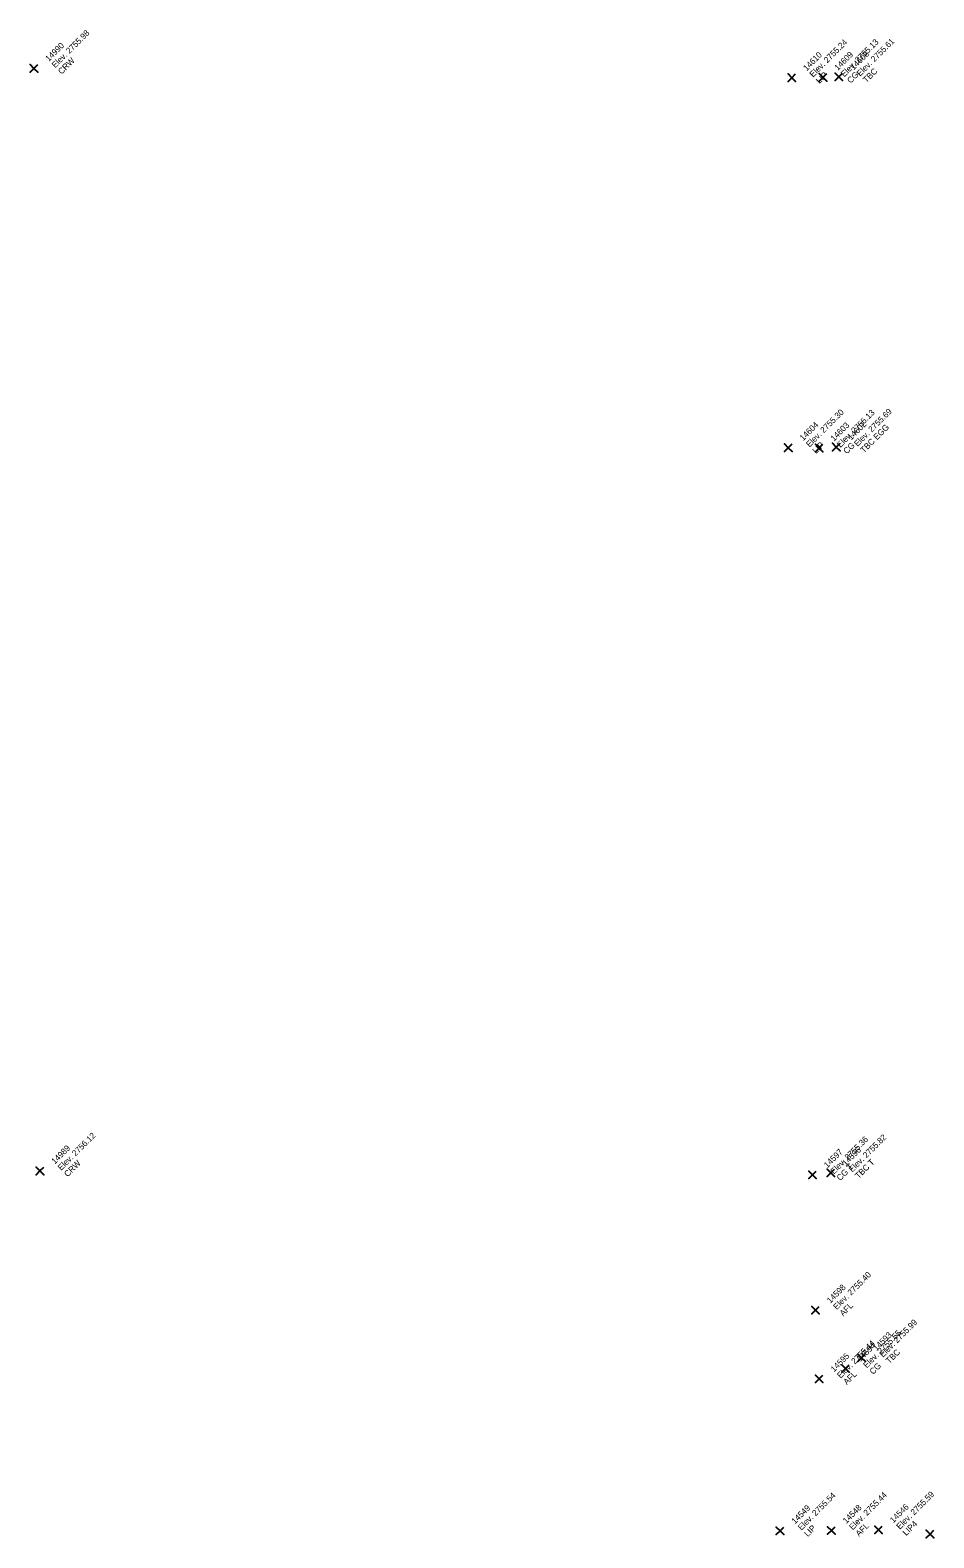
# Model space of a CAD drawing. Extents: x 2493999 to 2503109, y 700767 to 706646.
# Drawn here: x 2502292.9 to 2502328.9, y 703560.3 to 703620.3 of the extents above; entities that cross this region are included whole.
import ezdxf

# ---------------------------------------------------------------- set-up
doc = ezdxf.new("R2010")
doc.units = 0
doc.layers.add('ALG_CL_BLUE_Horiz', color=7, linetype='Continuous')
doc.layers.add('DES_SURFACE_Existing-Ground', color=7, linetype='Continuous')

msp = doc.modelspace()

# ---------------------------------------------------------------- linework, layer by layer
at = {"layer": 'ALG_CL_BLUE_Horiz'}
for points in [[(2502293.091, 703618.788), (2502292.941, 703618.938), (2502293.091, 703618.788), (2502292.941, 703618.638), (2502293.091, 703618.788), (2502293.241, 703618.638), (2502293.091, 703618.788), (2502293.241, 703618.938)], [(2502323.268, 703618.417), (2502323.118, 703618.567), (2502323.268, 703618.417), (2502323.118, 703618.267), (2502323.268, 703618.417), (2502323.418, 703618.267), (2502323.268, 703618.417), (2502323.418, 703618.567)], [(2502324.51, 703618.429), (2502324.36, 703618.579), (2502324.51, 703618.429), (2502324.36, 703618.279), (2502324.51, 703618.429), (2502324.66, 703618.279), (2502324.51, 703618.429), (2502324.66, 703618.579)], [(2502325.141, 703618.454), (2502324.991, 703618.604), (2502325.141, 703618.454), (2502324.991, 703618.304), (2502325.141, 703618.454), (2502325.291, 703618.304), (2502325.141, 703618.454), (2502325.291, 703618.604)], [(2502323.128, 703603.688), (2502322.978, 703603.838), (2502323.128, 703603.688), (2502322.978, 703603.538), (2502323.128, 703603.688), (2502323.278, 703603.538), (2502323.128, 703603.688), (2502323.278, 703603.838)], [(2502324.357, 703603.672), (2502324.207, 703603.822), (2502324.357, 703603.672), (2502324.207, 703603.522), (2502324.357, 703603.672), (2502324.507, 703603.522), (2502324.357, 703603.672), (2502324.507, 703603.822)], [(2502325.04, 703603.715), (2502324.89, 703603.865), (2502325.04, 703603.715), (2502324.89, 703603.565), (2502325.04, 703603.715), (2502325.19, 703603.565), (2502325.04, 703603.715), (2502325.19, 703603.865)], [(2502293.332, 703574.892), (2502293.182, 703575.042), (2502293.332, 703574.892), (2502293.182, 703574.742), (2502293.332, 703574.892), (2502293.482, 703574.742), (2502293.332, 703574.892), (2502293.482, 703575.042)], [(2502324.095, 703574.741), (2502323.945, 703574.891), (2502324.095, 703574.741), (2502323.945, 703574.591), (2502324.095, 703574.741), (2502324.245, 703574.591), (2502324.095, 703574.741), (2502324.245, 703574.891)], [(2502324.825, 703574.82), (2502324.675, 703574.97), (2502324.825, 703574.82), (2502324.675, 703574.67), (2502324.825, 703574.82), (2502324.975, 703574.67), (2502324.825, 703574.82), (2502324.975, 703574.97)], [(2502324.212, 703569.35), (2502324.062, 703569.5), (2502324.212, 703569.35), (2502324.062, 703569.2), (2502324.212, 703569.35), (2502324.362, 703569.2), (2502324.212, 703569.35), (2502324.362, 703569.5)], [(2502325.405, 703567.027), (2502325.255, 703567.177), (2502325.405, 703567.027), (2502325.255, 703566.877), (2502325.405, 703567.027), (2502325.555, 703566.877), (2502325.405, 703567.027), (2502325.555, 703567.177)], [(2502326.049, 703567.455), (2502325.899, 703567.605), (2502326.049, 703567.455), (2502325.899, 703567.305), (2502326.049, 703567.455), (2502326.199, 703567.305), (2502326.049, 703567.455), (2502326.199, 703567.605)], [(2502324.361, 703566.618), (2502324.211, 703566.768), (2502324.361, 703566.618), (2502324.211, 703566.468), (2502324.361, 703566.618), (2502324.511, 703566.468), (2502324.361, 703566.618), (2502324.511, 703566.768)], [(2502322.802, 703560.566), (2502322.652, 703560.716), (2502322.802, 703560.566), (2502322.652, 703560.416), (2502322.802, 703560.566), (2502322.952, 703560.416), (2502322.802, 703560.566), (2502322.952, 703560.716)], [(2502324.846, 703560.58), (2502324.696, 703560.73), (2502324.846, 703560.58), (2502324.696, 703560.43), (2502324.846, 703560.58), (2502324.996, 703560.43), (2502324.846, 703560.58), (2502324.996, 703560.73)], [(2502326.723, 703560.605), (2502326.573, 703560.755), (2502326.723, 703560.605), (2502326.573, 703560.455), (2502326.723, 703560.605), (2502326.873, 703560.455), (2502326.723, 703560.605), (2502326.873, 703560.755)], [(2502328.775, 703560.436), (2502328.625, 703560.586), (2502328.775, 703560.436), (2502328.625, 703560.286), (2502328.775, 703560.436), (2502328.925, 703560.286), (2502328.775, 703560.436), (2502328.925, 703560.586)]]:
    msp.add_lwpolyline(points, dxfattribs=at)

# ---------------------------------------------------------------- texts
at = {"layer": 'DES_SURFACE_Existing-Ground'}
for s, p in [('Elev. 2755.98', (2502293.94, 703618.788)), ('Elev. 2755.24', (2502324.117, 703618.417)), ('Elev. 2755.13', (2502325.359, 703618.429)), ('Elev. 2755.61', (2502325.99, 703618.454)), ('14990', (2502293.685, 703619.043)), ('14610', (2502323.862, 703618.672)), ('14609', (2502325.104, 703618.684)), ('14608', (2502325.735, 703618.709)), ('CRW', (2502294.194, 703618.533)), ('TBC', (2502326.244, 703618.199)), ('LIP', (2502324.371, 703618.162)), ('CG', (2502325.613, 703618.174)), ('Elev. 2755.30', (2502323.977, 703603.688)), ('Elev. 2755.13', (2502325.206, 703603.672)), ('Elev. 2755.69', (2502325.889, 703603.715)), ('14604', (2502323.722, 703603.943)), ('14603', (2502324.951, 703603.927)), ('14602', (2502325.634, 703603.97)), ('TBC EGG', (2502326.143, 703603.46)), ('LIP', (2502324.231, 703603.433)), ('CG', (2502325.46, 703603.417)), ('Elev. 2756.12', (2502294.181, 703574.892)), ('Elev. 2755.36', (2502324.944, 703574.741)), ('Elev. 2755.82', (2502325.674, 703574.82)), ('14989', (2502293.926, 703575.147)), ('14597', (2502324.689, 703574.996)), ('14596', (2502325.419, 703575.075)), ('CRW', (2502294.435, 703574.637)), ('CG T', (2502325.198, 703574.486)), ('TBC T', (2502325.928, 703574.565)), ('Elev. 2755.40', (2502325.061, 703569.35)), ('14598', (2502324.806, 703569.605)), ('AFL', (2502325.315, 703569.095)), ('Elev. 2755.99', (2502326.898, 703567.455)), ('Elev. 2755.55', (2502326.254, 703567.027)), ('14593', (2502326.643, 703567.71)), ('Elev. 2755.44', (2502325.21, 703566.618)), ('14594', (2502325.999, 703567.282)), ('TBC', (2502327.152, 703567.2)), ('14595', (2502324.955, 703566.873)), ('CG', (2502326.508, 703566.772)), ('AFL', (2502325.464, 703566.363)), ('Elev. 2755.54', (2502323.651, 703560.566)), ('Elev. 2755.44', (2502325.695, 703560.58)), ('Elev. 2755.59', (2502327.572, 703560.605)), ('14549', (2502323.396, 703560.821)), ('14548', (2502325.44, 703560.835)), ('14546', (2502327.317, 703560.86)), ('LIP', (2502323.905, 703560.311)), ('AFL', (2502325.949, 703560.325)), ('LIP4', (2502327.826, 703560.35))]:
    msp.add_text(s, height=0.24, rotation=45, dxfattribs=at).set_placement(p)

doc.saveas('drawing.dxf')
